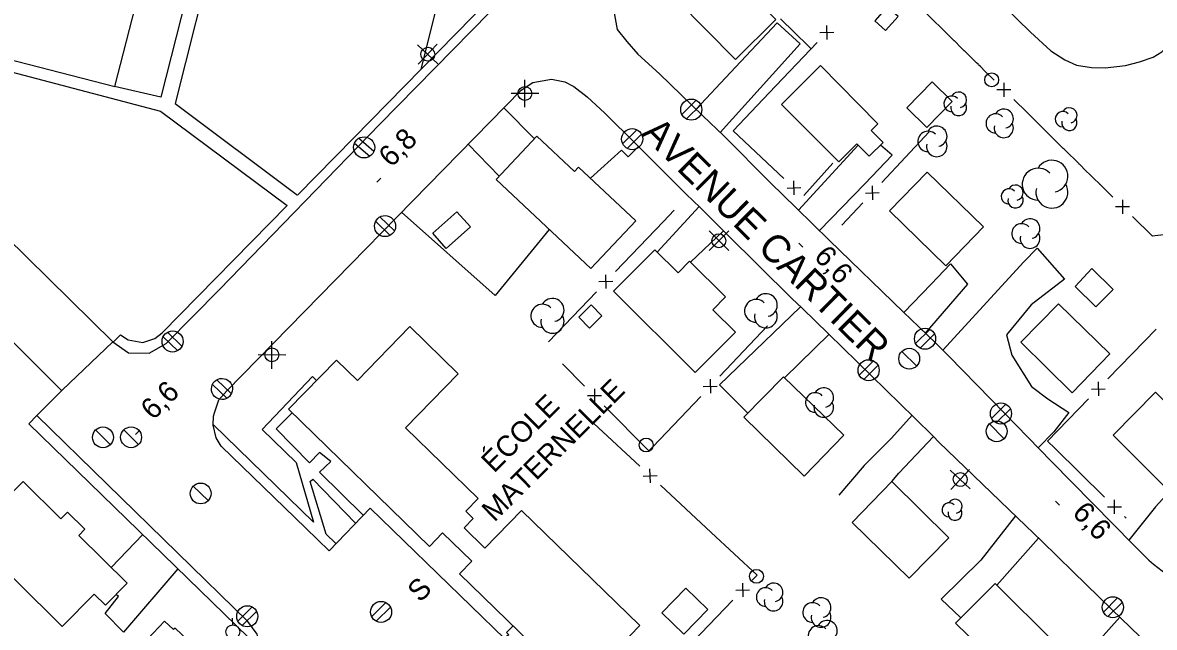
# Model space of a CAD drawing. Extents: x 381879 to 384696, y 5564785 to 5567594.
# Drawn here: x 382924 to 383086.9, y 5565288.9 to 5565376 of the extents above; entities that cross this region are included whole.
import ezdxf

# ---------------------------------------------------------------- set-up
doc = ezdxf.new("R2010")
doc.units = 0
for name, color, linetype in [('Niveau 19', 7, 'Continuous'), ('Niveau 21', 7, 'Continuous'), ('Niveau 22', 7, 'Continuous'), ('Niveau 3', 7, 'Continuous'), ('Niveau 31', 7, 'Continuous'), ('Niveau 36', 7, 'Continuous'), ('Niveau 37', 7, 'Continuous'), ('Niveau 44', 7, 'Continuous'), ('Niveau 52', 7, 'Continuous')]:
    doc.layers.add(name, color=color, linetype=linetype)

msp = doc.modelspace()

# ---------------------------------------------------------------- linework, layer by layer
at = {"layer": 'Niveau 19'}
for points in [[(383024.38, 5565360.2), (383035.9, 5565372.99), (383032.61, 5565376.01), (383025.9, 5565368.84), (383020.92, 5565363.55)], [(382993.26, 5565363.76), (382997.66, 5565359.3)], [(382936.92, 5565330.06), (382906.02, 5565360.46)], [(382988.11, 5565358.51), (382992.57, 5565353.9)], [(383012.63, 5565358.17), (383011.17, 5565356.7), (383010.17, 5565357.64), (383005.72, 5565353.6)], [(383044.27, 5565358.38), (383035.68, 5565349.02)], [(383038.7, 5565346.07), (383045.22, 5565352.82), (383049.16, 5565356.92), (383047.48, 5565358.4)], [(382898.62, 5565353.97), (382929.58, 5565323)], [(383021.35, 5565349.54), (383015.32, 5565342.97)], [(382999.77, 5565346.24), (382991.99, 5565336.72), (382978.52, 5565348.71)], [(383020.12, 5565341.53), (383024.86, 5565346.04)], [(383056.45, 5565328.85), (383068.11, 5565341.56), (383070.02, 5565343.56), (383073.98, 5565339.05), (383069.18, 5565335.35), (383065.64, 5565331.04), (383066.41, 5565328.14), (383069.24, 5565323.59), (383071.59, 5565321.83), (383074.58, 5565319.86), (383072.46, 5565317.06), (383070.18, 5565314.77)], [(383050.83, 5565334.27), (383054.79, 5565338.37), (383057.56, 5565341.29), (383059.99, 5565338.33), (383053.92, 5565331.31)], [(383035.98, 5565335.1), (383035.93, 5565335.05), (383024.3, 5565323.84)], [(383033.66, 5565324.85), (383040.07, 5565331.13)], [(383024.3, 5565323.84), (383028.37, 5565319.78)], [(383052.03, 5565319.46), (383049.05, 5565316.14), (383045.11, 5565312.21), (383041.47, 5565307.94)], [(383049.1, 5565309.9), (383050.12, 5565311.13), (383055.1, 5565316.4)], [(383089.1, 5565308.5), (383087.06, 5565306.26), (383083.23, 5565301.48)], [(383066.91, 5565304.98), (383061.94, 5565298.59), (383056.23, 5565292.98), (383058.98, 5565290.32)], [(382936.72, 5565297.55), (382941.26, 5565302.27)], [(383070.25, 5565301.74), (383064.24, 5565294.96)], [(382946.31, 5565297.36), (382938.49, 5565288.21), (382935.83, 5565290.92), (382937.75, 5565293.35), (382937.44, 5565293.66)], [(383081.96, 5565290.37), (383077.97, 5565285.9), (383072.98, 5565281.07), (383068.4, 5565276), (383073.75, 5565271.66), (383075.04, 5565273.01)]]:
    msp.add_lwpolyline(points, dxfattribs=at)
at = {"layer": 'Niveau 21'}
for points in [[(382945.1, 5565267.4), (382957.85, 5565280.55), (382958.51, 5565283.24), (382958.26, 5565285.83), (382957.71, 5565287.93), (382956.39, 5565289.74), (382926.01, 5565319.42), (382929.66, 5565323.08), (382936.92, 5565330.06), (382939.18, 5565328.45), (382942.16, 5565328.43), (382944.61, 5565329.79), (382952.32, 5565337.6), (382975.41, 5565361.41), (383014.89, 5565401.7), (383044.36, 5565431.82), (383061.2, 5565448.71)], [(383087.97, 5565444.43), (383083.16, 5565448.92), (383080.99, 5565449.74), (383077.87, 5565449.44), (383076.23, 5565448.4), (383074.1, 5565446.4), (383034.53, 5565405.66), (383010.08, 5565380.98), (383009.31, 5565379.13), (383009.17, 5565377.16), (383009.57, 5565375.02), (383010.97, 5565373.31), (383012.56, 5565371.48), (383015.67, 5565368.65)], [(383015.67, 5565368.65), (383021.9, 5565362.6)], [(382968.07, 5565299.93), (382964.72, 5565303.18), (382952.53, 5565314.99), (382951.8, 5565316.23), (382951.4, 5565318.03), (382951.46, 5565319.34), (382951.56, 5565319.82), (382952.2, 5565321.7), (382953.35, 5565322.99), (382995.75, 5565366.31), (382997.4, 5565367.43), (383000.13, 5565367.88), (383002.04, 5565367.52), (383003.3, 5565366.82), (383005.25, 5565365.32), (383007.8, 5565363)], [(383012.3, 5565358.5), (383007.8, 5565363)], [(383021.9, 5565362.6), (383024.9, 5565359.7)], [(383024.9, 5565359.7), (383031.6, 5565353), (383035.4, 5565349.3)], [(383021.5, 5565349.4), (383019.5, 5565351.3), (383012.3, 5565358.5)], [(383025.3, 5565345.6), (383021.5, 5565349.4)], [(383035.4, 5565349.3), (383040.1, 5565344.7)], [(383034.7, 5565336.3), (383025.3, 5565345.6)], [(383040.1, 5565344.7), (383050.8, 5565334.3)], [(383036.2, 5565334.9), (383034.7, 5565336.3)], [(383040, 5565331.2), (383036.2, 5565334.9)], [(383050.8, 5565334.3), (383053, 5565332.2)], [(383052.4, 5565319.1), (383040, 5565331.2)], [(383053, 5565332.2), (383055.5, 5565329.8)], [(383055.5, 5565329.8), (383057.3, 5565328), (383065.4, 5565319.7)], [(383065.4, 5565319.7), (383068.7, 5565316.3)], [(383055.1, 5565316.4), (383052.4, 5565319.1)], [(383067.2, 5565304.7), (383055.9, 5565315.6), (383055.1, 5565316.4)], [(383068.7, 5565316.3), (383072.1, 5565312.8)], [(383072.1, 5565312.8), (383083.9, 5565300.8)], [(383086.8, 5565298), (383089.3, 5565296.1), (383091.8, 5565295.1), (383094.3, 5565294.9), (383096.4, 5565295.4), (383098.1, 5565296.1), (383100.2, 5565297.4), (383103.5, 5565300.7), (383107.2, 5565304.3), (383110.1, 5565306.8), (383112.4, 5565308.7), (383114.6, 5565309.7), (383117.5, 5565310.6), (383120.4, 5565310.6), (383123.5, 5565310), (383124.1, 5565309.9)], [(383070.7, 5565301.3), (383067.2, 5565304.7)], [(383080.8, 5565291.5), (383075.2, 5565296.9), (383070.7, 5565301.3)], [(383083.9, 5565300.8), (383086.1, 5565298.6), (383086.8, 5565298)], [(383084.8, 5565287.6), (383080.8, 5565291.5)]]:
    msp.add_lwpolyline(points, dxfattribs=at)
at = {"layer": 'Niveau 22'}
for points in [[(382963.59, 5565351.22), (382971.66, 5565359.43), (383069.46, 5565459.27), (383069.48, 5565459.29)], [(382942.5, 5565387.41), (382949, 5565385.54), (382943.86, 5565365.3), (382937.16, 5565366.85)], [(382908.95, 5565372.45), (382943.82, 5565363.28), (382962.06, 5565349.67)], [(382937.01, 5565329.99), (382938.05, 5565331.04), (382939.16, 5565330.32), (382941.25, 5565329.93), (382942.98, 5565330.52), (382944.05, 5565331.36), (382962.06, 5565349.67)], [(382966.29, 5565324.48), (382965.71, 5565325.05), (382958.44, 5565317.43), (382963.33, 5565312.66), (382965.84, 5565304.05)], [(382973.01, 5565305.06), (382966.7, 5565311.27), (382968.33, 5565312.79), (382966.71, 5565314.11), (382965.27, 5565312.59), (382960.44, 5565317.51), (382962.75, 5565319.83)], [(382926.02, 5565319.41), (382924.86, 5565318.24), (382958.27, 5565285.71)], [(382951.4, 5565318.13), (382965.84, 5565304.05)], [(382967.66, 5565302.32), (382965.34, 5565309.91), (382965.75, 5565310.24), (382971.89, 5565303.9)], [(382967.66, 5565302.32), (382969.01, 5565301.05)], [(382994.58, 5565289.12), (382993.64, 5565288.16), (382993.96, 5565287.85), (382993.31, 5565287.34)]]:
    msp.add_lwpolyline(points, dxfattribs=at)
at = {"layer": 'Niveau 3'}
for p, q in [((382974.97, 5565353.04), (382975.54, 5565353.61)), ((383035.74, 5565344.25), (383036.31, 5565343.69)), ((382940.2, 5565316.68), (382940.77, 5565317.25)), ((383072.69, 5565307.07), (383073.26, 5565306.51))]:
    msp.add_line(p, q, dxfattribs=at)
at = {"layer": 'Niveau 31'}
for points in [[(382958.53, 5565443.51), (382938.53, 5565448.64), (382937.54, 5565444.79), (382903.33, 5565453.59), (382898.94, 5565436.52), (382902.71, 5565435.55), (382901.84, 5565432.17), (382922.64, 5565426.82), (382909.08, 5565374.08), (382937.21, 5565366.85), (382943.07, 5565389.63), (382940.9, 5565390.19), (382948.64, 5565420.18), (382952.3, 5565419.24)], [(383018.2, 5565379.2), (383023.9, 5565384.9), (383032.4, 5565376.5), (383026.6, 5565370.7)], [(383048.46, 5565378.31), (383046.66, 5565376.31), (383048.22, 5565374.9), (383050.02, 5565376.9)], [(383038.83, 5565369.86), (383047.11, 5565361.44), (383046.15, 5565360.49), (383047.86, 5565358.77), (383045.86, 5565356.78), (383044.08, 5565358.57), (383041.47, 5565355.97), (383033.21, 5565364.26)], [(383057.81, 5565364.67), (383054.17, 5565360.93), (383051.26, 5565363.77), (383054.9, 5565367.51)], [(383005.77, 5565340.59), (382992.13, 5565353.43), (382998, 5565359.66), (383003.41, 5565354.57), (383004.01, 5565355.21), (383012.23, 5565347.46)], [(383048.8, 5565348.9), (383054.2, 5565354.5), (383062.3, 5565346.6), (383056.9, 5565341)], [(382988.43, 5565346.6), (382984.96, 5565343.5), (382983, 5565345.69), (382986.47, 5565348.79)], [(383020.81, 5565325.63), (383009.03, 5565337.33), (383014.98, 5565343.31), (383018.33, 5565339.98), (383020, 5565341.65), (383025.18, 5565336.51), (383023.35, 5565334.67), (383026.59, 5565331.45)], [(383081, 5565337.6), (383078.5, 5565335.1), (383075.5, 5565338), (383077.9, 5565340.6)], [(383007.37, 5565333.8), (383005.56, 5565332.03), (383004.02, 5565333.6), (383005.83, 5565335.37)], [(383067.7, 5565330), (383073.1, 5565335.5), (383080.5, 5565328.3), (383075.1, 5565322.7)], [(383003.94, 5565280.01), (382986.87, 5565296.63), (382988.63, 5565298.43), (382984.43, 5565302.53), (382982.52, 5565300.57), (382962.24, 5565320.32), (382969.15, 5565327.42), (382972.16, 5565324.49), (382979.7, 5565332.23), (382986.68, 5565325.44), (382979.09, 5565317.64), (382989.54, 5565307.45), (382987.76, 5565305.63), (382988.83, 5565304.59), (382987.51, 5565303.24), (382990.5, 5565300.32), (382995.79, 5565305.75), (383012.84, 5565289.15)], [(383042.2, 5565316.6), (383036.5, 5565310.7), (383027.8, 5565319.2), (383033.5, 5565325)], [(383081, 5565316.6), (383087.1, 5565322.8), (383095.6, 5565314.3), (383089.4, 5565308.2)], [(382929.65, 5565289.01), (382916.35, 5565302.18), (382924.02, 5565309.93), (382929.46, 5565304.54), (382930.42, 5565305.51), (382932.93, 5565303.04), (382932.06, 5565302.16), (382939.03, 5565295.26), (382935.9, 5565292.11), (382934.27, 5565293.7)], [(383057.3, 5565301.8), (383051.6, 5565296), (383043.4, 5565304), (383049.1, 5565309.9)], [(383072.7, 5565286.6), (383067.1, 5565280.9), (383058.3, 5565289.5), (383064, 5565295.2)], [(383015.99, 5565290.99), (383019.45, 5565294.53), (383022.6, 5565291.46), (383019.14, 5565287.92)], [(382935.4, 5565280.3), (382941.1, 5565274.9), (382943, 5565277), (382945.3, 5565274.7), (382946.7, 5565276.2), (382944.6, 5565278.2), (382950.2, 5565284), (382949.4, 5565284.8), (382949.7, 5565285.2), (382945.9, 5565288.8), (382945.7, 5565288.6), (382944.4, 5565289.8)]]:
    msp.add_lwpolyline(points, close=True, dxfattribs=at)
at = {"layer": 'Niveau 36'}
for p, q in [((382980.82, 5565372.84), (382983.73, 5565370.12)), ((382980.92, 5565370.03), (382983.64, 5565372.94)), ((382996.28, 5565363.83), (382996.29, 5565367.81)), ((382998.28, 5565365.81), (382994.29, 5565365.83)), ((383020.93, 5565364.84), (383018.87, 5565362.8)), ((383019.53, 5565362.16), (383021.59, 5565364.2)), ((383012.41, 5565360.59), (383010.35, 5565358.55)), ((382971.74, 5565358.66), (382973.93, 5565356.77)), ((382974.52, 5565357.48), (382972.33, 5565359.37)), ((383011.01, 5565357.91), (383013.07, 5565359.95)), ((382974.79, 5565347.38), (382976.87, 5565345.36)), ((382977.49, 5565346.04), (382975.41, 5565348.06)), ((383025.62, 5565346.02), (383022.8, 5565343.2)), ((383025.62, 5565343.2), (383022.8, 5565346.02)), ((382946.9, 5565329.43), (382944.82, 5565331.45)), ((383054.58, 5565331.83), (383052.52, 5565329.79)), ((383053.18, 5565329.15), (383055.24, 5565331.19)), ((382944.2, 5565330.77), (382946.28, 5565328.75)), ((382959.85, 5565326.16), (382959.86, 5565330.14)), ((382961.85, 5565328.14), (382957.86, 5565328.16)), ((383052.69, 5565326.55), (383050.57, 5565328.67)), ((383046.46, 5565327.29), (383044.4, 5565325.25)), ((383045.06, 5565324.61), (383047.12, 5565326.65)), ((382954.01, 5565322.57), (382951.93, 5565324.59)), ((382951.31, 5565323.91), (382953.39, 5565321.89)), ((383065.52, 5565321.05), (383063.46, 5565319.01)), ((383064.12, 5565318.37), (383066.18, 5565320.41)), ((383065.28, 5565316.09), (383063.16, 5565318.21)), ((382936.59, 5565315.22), (382934.47, 5565317.34)), ((382940.64, 5565315.23), (382938.52, 5565317.35)), ((383057.49, 5565311.56), (383060.4, 5565308.84)), ((383057.59, 5565308.75), (383060.31, 5565311.66)), ((382950.68, 5565307.16), (382948.52, 5565309.24)), ((382956.99, 5565291.84), (382954.93, 5565289.8)), ((382976.26, 5565292.47), (382974.2, 5565290.43)), ((383081.63, 5565293.14), (383079.57, 5565291.1)), ((383080.23, 5565290.46), (383082.29, 5565292.5)), ((382954.14, 5565290.24), (382954.19, 5565289.24)), ((382955.59, 5565289.16), (382957.65, 5565291.2)), ((382974.86, 5565289.79), (382976.92, 5565291.83))]:
    msp.add_line(p, q, dxfattribs=at)
for centre, radius in [((383063.49, 5565367.8), 1), ((382996.28, 5565365.83), 1), ((383020.24, 5565363.5), 1.52), ((383011.72, 5565359.25), 1.52), ((383024.2, 5565344.61), 1), ((383053.89, 5565330.49), 1.52), ((382959.85, 5565328.16), 1), ((383051.62, 5565327.61), 1.5), ((383045.77, 5565325.95), 1.52), ((383064.83, 5565319.71), 1.52), ((383064.21, 5565317.15), 1.5), ((382935.52, 5565316.28), 1.5), ((382939.57, 5565316.29), 1.5), ((383013.75, 5565315.18), 1), ((382949.59, 5565308.2), 1.5), ((383029.62, 5565296.26), 1), ((382956.3, 5565290.5), 1.52), ((382975.57, 5565291.13), 1.52), ((383080.94, 5565291.8), 1.52), ((382954.22, 5565288.25), 1)]:
    msp.add_circle(centre, radius, dxfattribs=at)
for centre, major_axis, ratio in [((382982.29, 5565371.48), (-0.048, -0.999), 0.999982), ((382973.13, 5565358.06), (0.01, 1.52), 0.999982), ((382976.14, 5565346.72), (-0.02, -1.52), 0.999984), ((382945.55, 5565330.09), (0.02, 1.52), 0.999984), ((382952.66, 5565323.25), (-0.02, -1.52), 0.999984), ((383058.96, 5565310.2), (-0.048, -0.999), 0.999982)]:
    msp.add_ellipse(centre, major_axis=major_axis, ratio=ratio, dxfattribs=at)
at = {"layer": 'Niveau 37'}
for p, q in [((383039.71, 5565375.61), (383039.76, 5565373.61)), ((383038.73, 5565374.59), (383040.74, 5565374.64)), ((383065.25, 5565367.35), (383065.26, 5565365.35)), ((383066.26, 5565366.36), (383064.25, 5565366.34)), ((383034.02, 5565352.19), (383036.02, 5565352.26)), ((383035.05, 5565351.22), (383034.99, 5565353.22)), ((383046.26, 5565352.52), (383046.34, 5565350.52)), ((383045.3, 5565351.48), (383047.3, 5565351.56)), ((383082.33, 5565350.5), (383082.35, 5565348.5)), ((383083.34, 5565349.51), (383081.34, 5565349.5)), ((383007.97, 5565337.71), (383007.92, 5565339.71)), ((383008.95, 5565338.74), (383006.94, 5565338.69)), ((383022.94, 5565324.65), (383023, 5565322.65)), ((383006.29, 5565323.25), (383006.28, 5565321.24)), ((383021.97, 5565323.62), (383023.97, 5565323.67)), ((383077.84, 5565323.24), (383079.84, 5565323.27)), ((383078.82, 5565324.26), (383078.85, 5565322.25)), ((383007.29, 5565322.24), (383005.28, 5565322.25)), ((383014.35, 5565309.74), (383014.28, 5565311.75)), ((383013.31, 5565310.71), (383015.32, 5565310.78)), ((383081.19, 5565305.27), (383081.17, 5565307.28)), ((383080.18, 5565306.26), (383082.18, 5565306.28)), ((383027.61, 5565295.28), (383027.65, 5565293.28)), ((383026.63, 5565294.26), (383028.63, 5565294.3))]:
    msp.add_line(p, q, dxfattribs=at)
for points in [[(383056.71, 5565374.78), (383050.52, 5565380.88), (383049.59, 5565381.8)], [(383033.08, 5565376.58), (383037.13, 5565372.62), (383037.5, 5565372.26)], [(383063.83, 5565367.76), (383062.57, 5565369), (383061.86, 5565369.7), (383061.64, 5565369.92), (383061.59, 5565369.97), (383061.53, 5565370.03), (383061.29, 5565370.26), (383061.06, 5565370.49), (383061.02, 5565370.53), (383060.98, 5565370.57), (383060.06, 5565371.48), (383059.57, 5565371.96), (383059.56, 5565371.97), (383059.55, 5565371.98), (383059.05, 5565372.47), (383058.12, 5565373.39), (383058.09, 5565373.42), (383058.05, 5565373.46), (383057.47, 5565374.03), (383056.71, 5565374.78)], [(383038.36, 5565373.16), (383031.47, 5565365.91)], [(383031.47, 5565365.91), (383026.27, 5565360.44)], [(383073.8, 5565357.92), (383073.51, 5565358.21), (383072.51, 5565359.19), (383068.58, 5565363.07), (383066.68, 5565364.95)], [(383026.27, 5565360.44), (383033.56, 5565353.59)], [(383054.48, 5565360.3), (383047.66, 5565352.98)], [(383080.92, 5565350.91), (383079.14, 5565352.66), (383079.13, 5565352.67), (383079.12, 5565352.68), (383079.12, 5565352.69), (383079.1, 5565352.7), (383079.09, 5565352.71), (383078.12, 5565353.66), (383077.63, 5565354.15), (383077.62, 5565354.16), (383077.11, 5565354.65), (383076.13, 5565355.62), (383076.12, 5565355.63), (383076.11, 5565355.64), (383076.06, 5565355.69), (383075.98, 5565355.77), (383074.1, 5565357.63), (383073.93, 5565357.79), (383073.8, 5565357.92)], [(383036.46, 5565351.14), (383040.63, 5565355.77)], [(383016.22, 5565347.4), (383017.75, 5565349.01)], [(383044.94, 5565350.06), (383041.93, 5565346.83)], [(383009.32, 5565340.16), (383016.22, 5565347.4)], [(383092.55, 5565345.98), (383086.65, 5565345.25), (383083.76, 5565348.1)], [(382999.67, 5565330.02), (383006.57, 5565337.26)], [(383031.22, 5565332.36), (383024.34, 5565325.1)], [(383087.19, 5565331.87), (383080.23, 5565324.69)], [(383004.88, 5565323.66), (383001.71, 5565326.86)], [(383021.59, 5565322.19), (383014.72, 5565314.93)], [(383077.44, 5565321.82), (383071.53, 5565315.72), (383072.61, 5565314.67)], [(383014.72, 5565314.93), (383014.14, 5565314.32), (383007.69, 5565320.82)], [(383005.53, 5565318.92), (383012.85, 5565312.11)], [(383072.61, 5565314.67), (383079.75, 5565307.67)], [(383015.78, 5565309.38), (383023.1, 5565302.57)], [(383082.61, 5565304.87), (383082.86, 5565304.63)], [(383023.1, 5565302.57), (383029.7, 5565296.43), (383029.02, 5565295.72)], [(383026.24, 5565292.84), (383019.31, 5565285.63)]]:
    msp.add_lwpolyline(points, dxfattribs=at)
at = {"layer": 'Niveau 44'}
for centre, radius, start, end in [((383057.75, 5565364.33), 1.14, 44.1153, 269.8039), ((383058.74, 5565364.9), 1.14, 282.2692, 149.7262), ((383058.74, 5565363.76), 1.14, 166.9368, 29.6212), ((383065.23, 5565362.21), 1.38, 282.2692, 149.7262), ((383074.68, 5565362.67), 1.1, 282.2692, 149.7262), ((383064.05, 5565361.52), 1.38, 44.1153, 269.8039), ((383073.73, 5565362.13), 1.1, 44.1153, 269.8039), ((383074.68, 5565361.58), 1.1, 166.9368, 29.6212), ((383054.33, 5565358.92), 1.47, 44.1153, 269.8039), ((383055.59, 5565359.66), 1.47, 282.2692, 149.7262), ((383065.23, 5565360.83), 1.38, 166.9368, 29.6212), ((383055.59, 5565358.19), 1.47, 166.9368, 29.6212), ((383072.16, 5565353.9), 2.3, 282.2692, 149.7262), ((383070.19, 5565352.76), 2.3, 44.1153, 269.8039), ((383066.92, 5565351.54), 1.1, 282.2692, 149.7262), ((383072.16, 5565351.61), 2.3, 166.9368, 29.6212), ((383065.97, 5565350.99), 1.1, 44.1153, 269.8039), ((383066.92, 5565350.43), 1.1, 166.9368, 29.6212), ((383069.02, 5565346.35), 1.42, 282.2692, 149.7262), ((383067.8, 5565345.64), 1.42, 44.1153, 269.8039), ((383069.02, 5565344.93), 1.42, 166.9368, 29.6212), ((383000.25, 5565334.63), 1.67, 282.2692, 149.7262), ((383029.56, 5565334.51), 1.65, 44.1153, 269.8039), ((383030.97, 5565335.33), 1.65, 282.2692, 149.7262), ((382998.81, 5565333.79), 1.67, 44.1153, 269.8039), ((383030.97, 5565333.69), 1.65, 166.9368, 29.6212), ((383000.25, 5565332.95), 1.67, 166.9368, 29.6212), ((383039.31, 5565322.01), 1.41, 282.2692, 149.7262), ((383038.09, 5565321.3), 1.41, 44.1153, 269.8039), ((383039.31, 5565320.59), 1.41, 166.9368, 29.6212), ((383057.35, 5565305.84), 1.01, 44.1153, 269.8039), ((383058.21, 5565306.35), 1.01, 282.2692, 149.7262), ((383058.21, 5565305.34), 1.01, 166.9368, 29.6212), ((383032.09, 5565293.95), 1.34, 282.2692, 149.7262), ((383030.94, 5565293.28), 1.34, 44.1153, 269.8039), ((383032.09, 5565292.61), 1.34, 166.9368, 29.6212), ((383037.71, 5565291.04), 1.42, 44.1153, 269.8039), ((383038.93, 5565291.75), 1.42, 282.2692, 149.7262), ((383038.93, 5565290.33), 1.42, 166.9368, 29.6212), ((383038.53, 5565287.68), 1.47, 44.1153, 269.8039), ((383039.79, 5565288.42), 1.47, 282.2692, 149.7262)]:
    msp.add_arc(centre, radius, start, end, dxfattribs=at)
at = {"layer": 'Niveau 52'}
for points in [[(383022.63, 5565417.33), (383020.54, 5565417.86), (383021.77, 5565423.72), (382977.12, 5565434.88), (382975.33, 5565426.68), (382957.72, 5565411.28), (382945.94, 5565364.4), (382963.54, 5565351.17)], [(383035.85, 5565407.02), (383053.65, 5565389.72), (383069.09, 5565374.65), (383072.03, 5565371.98), (383074.04, 5565370.66), (383075.68, 5565369.9), (383077.84, 5565369.58), (383079.81, 5565369.53), (383082.77, 5565369.84), (383084.78, 5565370.4), (383086.76, 5565371.04), (383088, 5565371.83), (383090.86, 5565374.74), (383109.19, 5565356.9), (383127.51, 5565375.57), (383138.19, 5565386.44), (383135.18, 5565389.09), (383134.99, 5565389.62), (383134.88, 5565389.92), (383135.05, 5565390.15), (383139.44, 5565394.63)], [(382981.35, 5565369.32), (382990.31, 5565405.09), (383006.28, 5565401.22), (383011.18, 5565405.77)], [(382968.07, 5565299.93), (382973.98, 5565306.07), (382993.39, 5565287.26), (382987.2, 5565281.06)]]:
    msp.add_lwpolyline(points, dxfattribs=at)

# ---------------------------------------------------------------- texts
at = {"layer": 'Niveau 21'}
msp.add_text('AVENUE CARTIER', height=4, rotation=315.3941, dxfattribs=at).set_placement((383012.91, 5565359.93))
at = {"layer": 'Niveau 3'}
for s, rotation, p in [('6,8  ', 44.7717, (382977.02, 5565355.06)), ('6,6  ', 312.9725, (383037.77, 5565342.21)), ('6,6  ', 44.7717, (382942.76, 5565318.65)), ('6,6  ', 313.3625, (383074.96, 5565305.28))]:
    msp.add_text(s, height=3, rotation=rotation, dxfattribs=at).set_placement(p)
at = {"layer": 'Niveau 31'}
for s, p in [('MATERNELLE', (382991.88, 5565303.99)), ('ÉCOLE', (382991.82, 5565311.04))]:
    msp.add_text(s, height=3, rotation=44.7717, dxfattribs=at).set_placement(p)
at = {"layer": 'Niveau 52'}
msp.add_text('S', height=3, rotation=44.7717, dxfattribs=at).set_placement((382981.18, 5565292.38))

doc.saveas('drawing.dxf')
